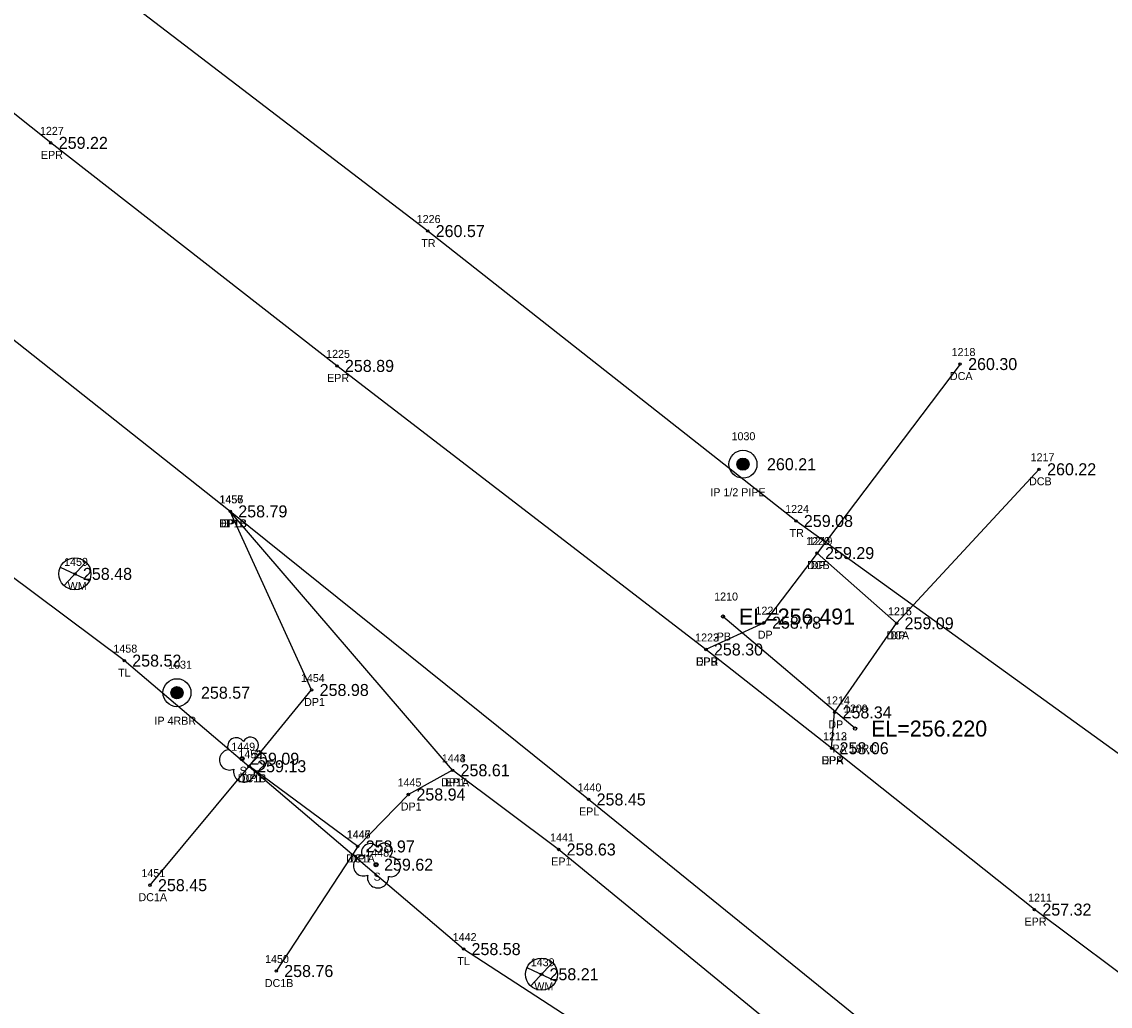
# Model space of a CAD drawing. Extents: x 1961231 to 1962574, y 799865 to 801120.
# Drawn here: x 1961812.2 to 1961948.3, y 800591.6 to 800714.6 of the extents above; entities that cross this region are included whole.
import ezdxf

# ---------------------------------------------------------------- set-up
doc = ezdxf.new("R2010")
doc.units = 0
for name, color, linetype in [('RD_EX_Conc', 7, 'Continuous'), ('RD_EX_Conc_txCode', 7, 'Continuous'), ('RD_EX_DR_Pipe', 7, 'Continuous'), ('RD_EX_DR_Pipe_txCode', 7, 'Continuous'), ('RD_EX_Driveway', 7, 'Continuous'), ('RD_EX_Driveway_txCode', 7, 'Continuous'), ('RD_EX_DV_Prop_txCode', 7, 'Continuous'), ('RD_EX_DV_PropPin', 7, 'Continuous'), ('RD_EX_Road', 7, 'Continuous'), ('RD_EX_Road_txCode', 7, 'Continuous'), ('RD_EX_TX_Conc_ELEV', 7, 'Continuous'), ('RD_EX_TX_Driveway_ELEV', 7, 'Continuous'), ('RD_EX_TX_DV_Prop_ELEV', 7, 'Continuous'), ('RD_EX_TX_Road_ELEV', 7, 'Continuous'), ('RD_EX_TX_UT_ELEV', 7, 'Continuous'), ('RD_EX_TX_VEG_ELEV', 7, 'Continuous'), ('RD_EX_UT', 7, 'Continuous'), ('RD_EX_UT_txCode', 7, 'Continuous'), ('RD_EX_VEG', 7, 'Continuous'), ('RD_EX_VEG_txCode', 7, 'Continuous'), ('RD_SMD_Locator', 7, 'Continuous'), ('RD_TX_Pipe_ElevEX', 7, 'Continuous')]:
    doc.layers.add(name, color=color, linetype=linetype)

msp = doc.modelspace()

# ---------------------------------------------------------------- linework, layer by layer
at = {"layer": 'RD_EX_Conc'}
for p, q in [((1961929.49, 800671.84), (1961911.62, 800648.22)), ((1961921.55, 800639.44), (1961939.36, 800658.69)), ((1961828.26, 800606.72), (1961840.65, 800621.58)), ((1961854.21, 800611.56), (1961844.03, 800595.99))]:
    msp.add_line(p, q, dxfattribs=at)
at = {"layer": 'RD_EX_DR_Pipe'}
msp.add_line((1961916.37, 800626.29), (1961899.86, 800640.29), dxfattribs=at)
at = {"layer": 'RD_EX_Driveway'}
for points in [[(1961866.07, 800621.08), (1961860.55, 800618.05), (1961854.21, 800611.56), (1961840.65, 800621.58), (1961848.46, 800631.11), (1961838.29, 800653.43)], [(1961913.43, 800623.83), (1961913.8, 800628.31), (1961921.55, 800639.44), (1961911.62, 800648.22), (1961904.99, 800639.52), (1961897.73, 800636.17)]]:
    msp.add_lwpolyline(points, dxfattribs=at)
at = {"layer": 'RD_EX_DV_PropPin'}
for p, q in [((1961902.15, 800658.59), (1961902.15, 800660.06)), ((1961902.18, 800658.58), (1961902.18, 800660.06)), ((1961902.22, 800658.58), (1961902.22, 800660.07)), ((1961902.25, 800658.57), (1961902.25, 800660.08)), ((1961902.29, 800658.57), (1961902.29, 800660.08)), ((1961902.32, 800658.56), (1961902.32, 800660.08)), ((1961902.36, 800658.56), (1961902.36, 800660.08)), ((1961902.39, 800658.56), (1961902.39, 800660.08)), ((1961902.43, 800658.57), (1961902.43, 800660.08)), ((1961902.46, 800658.57), (1961902.46, 800660.08)), ((1961902.5, 800658.58), (1961902.5, 800660.07)), ((1961902.53, 800658.58), (1961902.53, 800660.06)), ((1961902.57, 800658.59), (1961902.57, 800660.06)), ((1961901.62, 800659.13), (1961901.62, 800659.52)), ((1961901.66, 800659.03), (1961901.66, 800659.62)), ((1961901.69, 800658.95), (1961901.69, 800659.69)), ((1961901.73, 800658.9), (1961901.73, 800659.75)), ((1961901.76, 800658.85), (1961901.76, 800659.8)), ((1961901.8, 800658.81), (1961901.8, 800659.84)), ((1961901.83, 800658.77), (1961901.83, 800659.87)), ((1961901.87, 800658.74), (1961901.87, 800659.91)), ((1961901.9, 800658.71), (1961901.9, 800659.93)), ((1961901.94, 800658.69), (1961901.94, 800659.96)), ((1961901.97, 800658.67), (1961901.97, 800659.98)), ((1961902.01, 800658.65), (1961902.01, 800660)), ((1961902.04, 800658.63), (1961902.04, 800660.02)), ((1961902.08, 800658.62), (1961902.08, 800660.03)), ((1961902.11, 800658.6), (1961902.11, 800660.04)), ((1961902.6, 800658.6), (1961902.6, 800660.04)), ((1961902.64, 800658.62), (1961902.64, 800660.03)), ((1961902.67, 800658.63), (1961902.67, 800660.02)), ((1961902.71, 800658.65), (1961902.71, 800660)), ((1961902.74, 800658.67), (1961902.74, 800659.98)), ((1961902.78, 800658.69), (1961902.78, 800659.96)), ((1961902.81, 800658.71), (1961902.81, 800659.93)), ((1961902.85, 800658.74), (1961902.85, 800659.91)), ((1961902.88, 800658.77), (1961902.88, 800659.87)), ((1961902.92, 800658.81), (1961902.92, 800659.84)), ((1961902.95, 800658.85), (1961902.95, 800659.8)), ((1961902.99, 800658.9), (1961902.99, 800659.75)), ((1961903.02, 800658.95), (1961903.02, 800659.69)), ((1961903.06, 800659.03), (1961903.06, 800659.62)), ((1961903.09, 800659.13), (1961903.09, 800659.52)), ((1961831.42, 800630.03), (1961831.42, 800631.5)), ((1961831.46, 800630.02), (1961831.46, 800631.51)), ((1961831.49, 800630.02), (1961831.49, 800631.51)), ((1961831.53, 800630.01), (1961831.53, 800631.52)), ((1961831.56, 800630.01), (1961831.56, 800631.52)), ((1961831.6, 800630.01), (1961831.6, 800631.53)), ((1961831.63, 800630), (1961831.63, 800631.53)), ((1961831.67, 800630.01), (1961831.67, 800631.53)), ((1961831.7, 800630.01), (1961831.7, 800631.52)), ((1961831.74, 800630.01), (1961831.74, 800631.52)), ((1961831.77, 800630.02), (1961831.77, 800631.51)), ((1961831.81, 800630.02), (1961831.81, 800631.51)), ((1961831.84, 800630.03), (1961831.84, 800631.5)), ((1961830.9, 800630.57), (1961830.9, 800630.96)), ((1961830.93, 800630.47), (1961830.93, 800631.06)), ((1961830.97, 800630.4), (1961830.97, 800631.13)), ((1961831, 800630.34), (1961831, 800631.19)), ((1961831.04, 800630.29), (1961831.04, 800631.24)), ((1961831.07, 800630.25), (1961831.07, 800631.28)), ((1961831.11, 800630.21), (1961831.11, 800631.32)), ((1961831.14, 800630.18), (1961831.14, 800631.35)), ((1961831.18, 800630.16), (1961831.18, 800631.38)), ((1961831.21, 800630.13), (1961831.21, 800631.4)), ((1961831.25, 800630.11), (1961831.25, 800631.42)), ((1961831.28, 800630.09), (1961831.28, 800631.44)), ((1961831.32, 800630.07), (1961831.32, 800631.46)), ((1961831.35, 800630.06), (1961831.35, 800631.47)), ((1961831.39, 800630.04), (1961831.39, 800631.49)), ((1961831.88, 800630.04), (1961831.88, 800631.49)), ((1961831.91, 800630.06), (1961831.91, 800631.47)), ((1961831.95, 800630.07), (1961831.95, 800631.46)), ((1961831.98, 800630.09), (1961831.98, 800631.44)), ((1961832.02, 800630.11), (1961832.02, 800631.42)), ((1961832.05, 800630.13), (1961832.05, 800631.4)), ((1961832.09, 800630.16), (1961832.09, 800631.38)), ((1961832.12, 800630.18), (1961832.12, 800631.35)), ((1961832.16, 800630.21), (1961832.16, 800631.32)), ((1961832.19, 800630.25), (1961832.19, 800631.28)), ((1961832.23, 800630.29), (1961832.23, 800631.24)), ((1961832.26, 800630.34), (1961832.26, 800631.19)), ((1961832.3, 800630.4), (1961832.3, 800631.13)), ((1961832.33, 800630.47), (1961832.33, 800631.06)), ((1961832.37, 800630.57), (1961832.37, 800630.96))]:
    msp.add_line(p, q, dxfattribs=at)
for centre, radius in [((1961902.36, 800659.32), 1.75), ((1961902.36, 800659.32), 0.761), ((1961831.63, 800630.77), 1.75), ((1961831.63, 800630.77), 0.761)]:
    msp.add_circle(centre, radius, dxfattribs=at)
at = {"layer": 'RD_EX_Road'}
for points in [[(1962276.74, 800366.53), (1962275.76, 800367.28), (1962226.46, 800400.66), (1962183.05, 800429.73), (1962145.98, 800455.38), (1962104.4, 800484.06), (1962056.77, 800517.94), (1962023.95, 800541.05), (1961991.87, 800563.56), (1961983.89, 800569.94), (1961938.77, 800603.67), (1961913.43, 800623.83), (1961897.73, 800636.17), (1961851.62, 800671.61), (1961815.86, 800699.48), (1961795.77, 800715.49), (1961771.88, 800733.73), (1961750.77, 800750.96), (1961735.63, 800762.82), (1961702.92, 800788.52)], [(1962241.79, 800315.68), (1962238.35, 800317.6), (1962189.92, 800352.69), (1962151.64, 800383.49), (1962113.78, 800416.39), (1962074.11, 800451.29), (1962034.78, 800486.96), (1962017.07, 800503.17), (1961999.46, 800519.25), (1961962.48, 800552.12), (1961937.08, 800573.11), (1961923.19, 800584.9), (1961883.07, 800617.43), (1961838.29, 800653.43), (1961801.42, 800682.57), (1961728.41, 800740.86), (1961722.95, 800745.11), (1961689.13, 800771.93)], [(1961992.53, 800418.34), (1962000.94, 800437), (1962011.01, 800464.81), (1962016.84, 800481.64), (1962015.31, 800499.65), (1961996.99, 800516.71), (1961979.47, 800530.76), (1961969.8, 800538.75), (1961958.28, 800547.16), (1961941.07, 800560.82), (1961925.41, 800573.41), (1961918.19, 800579.25), (1961879.32, 800611.18), (1961866.07, 800621.08), (1961838.29, 800653.43)]]:
    msp.add_lwpolyline(points, dxfattribs=at)
at = {"layer": 'RD_EX_UT'}
for p, q in [((1961817.05, 800646.46), (1961820.68, 800644.75)), ((1961817.53, 800644.16), (1961820.19, 800647.06)), ((1961875.35, 800596.42), (1961878.98, 800594.71)), ((1961875.83, 800594.13), (1961878.5, 800597.02))]:
    msp.add_line(p, q, dxfattribs=at)
for centre in [(1961818.88, 800645.62), (1961877.18, 800595.59)]:
    msp.add_circle(centre, 2, dxfattribs=at)
at = {"layer": 'RD_EX_VEG'}
for points in [[(1961991.65, 800601.73), (1961952.54, 800620.78), (1961908.97, 800652.23), (1961862.96, 800688.46), (1961806.36, 800731.71)], [(1961986.16, 800417.05), (1962008.73, 800486.69), (1961986.14, 800509.28), (1961949.4, 800540.42), (1961909.42, 800571.42), (1961867.44, 800598.73), (1961825.04, 800634.78), (1961788.24, 800662.23), (1961745.49, 800697.38)]]:
    msp.add_lwpolyline(points, dxfattribs=at)
for centre in [(1961839.77, 800622.52), (1961856.51, 800609.28)]:
    msp.add_circle(centre, 0.25, dxfattribs=at)
for centre, radius, start, end in [((1961839.04, 800624.07), 1.08, 34.9763, 204.756), ((1961840.81, 800624.22), 0.995, 308.7626, 152.0467), ((1961838.2, 800622.37), 1.26, 96.4518, 294.734), ((1961841.6, 800622.24), 1.22, 256.5667, 98.1046), ((1961840.01, 800620.92), 1.32, 166.8827, 5.7589), ((1961855.78, 800610.83), 1.08, 34.9763, 204.756), ((1961857.55, 800610.98), 0.995, 308.7626, 152.0467), ((1961854.94, 800609.13), 1.26, 96.4518, 294.734), ((1961858.34, 800609), 1.22, 256.5667, 98.1046), ((1961856.75, 800607.69), 1.32, 166.8827, 5.7589)]:
    msp.add_arc(centre, radius, start, end, dxfattribs=at)
at = {"layer": 'RD_SMD_Locator'}
for centre, radius in [((1961815.86, 800699.48), 0.15), ((1961862.96, 800688.46), 0.15), ((1961851.62, 800671.61), 0.15), ((1961929.49, 800671.84), 0.15), ((1961902.36, 800659.32), 0.15), ((1961939.36, 800658.69), 0.15), ((1961838.29, 800653.43), 0.15), ((1961838.29, 800653.43), 0.15), ((1961838.29, 800653.43), 0.15), ((1961908.97, 800652.23), 0.15), ((1961911.62, 800648.22), 0.15), ((1961911.62, 800648.22), 0.15), ((1961818.88, 800645.62), 0.15), ((1961899.86, 800640.29), 0.2), ((1961904.99, 800639.52), 0.15), ((1961921.55, 800639.44), 0.15), ((1961921.55, 800639.44), 0.15), ((1961897.73, 800636.17), 0.15), ((1961897.73, 800636.17), 0.15), ((1961825.04, 800634.78), 0.15), ((1961831.63, 800630.77), 0.15), ((1961848.46, 800631.11), 0.15), ((1961913.8, 800628.31), 0.15), ((1961916.37, 800626.29), 0.2), ((1961913.43, 800623.83), 0.15), ((1961913.43, 800623.83), 0.15), ((1961839.77, 800622.52), 0.15), ((1961840.65, 800621.58), 0.15), ((1961840.65, 800621.58), 0.15), ((1961866.07, 800621.08), 0.15), ((1961866.07, 800621.08), 0.15), ((1961860.55, 800618.05), 0.15), ((1961883.07, 800617.43), 0.15), ((1961854.21, 800611.56), 0.15), ((1961854.21, 800611.56), 0.15), ((1961879.32, 800611.18), 0.15), ((1961856.51, 800609.28), 0.15), ((1961828.26, 800606.72), 0.15), ((1961938.77, 800603.67), 0.15), ((1961867.44, 800598.73), 0.15), ((1961844.03, 800595.99), 0.15), ((1961877.18, 800595.59), 0.15)]:
    msp.add_circle(centre, radius, dxfattribs=at)

# ---------------------------------------------------------------- texts
at = {"layer": 'RD_EX_Conc_txCode'}
for s, p in [('1218', (1961928.43, 800672.84)), ('DCA', (1961928.22, 800669.84)), ('1217', (1961938.3, 800659.69)), ('DCB', (1961938.11, 800656.69)), ('1219', (1961910.56, 800649.22)), ('DCB', (1961910.37, 800646.22)), ('1216', (1961920.47, 800640.44)), ('DCA', (1961920.29, 800637.44)), ('1452', (1961839.31, 800622.58)), ('DC1B', (1961839.24, 800619.58)), ('1447', (1961852.86, 800612.56)), ('DC1A', (1961852.78, 800609.56)), ('1451', (1961827.19, 800607.72)), ('DC1A', (1961826.82, 800604.72)), ('1450', (1961842.64, 800596.99)), ('DC1B', (1961842.61, 800593.99))]:
    msp.add_text(s, height=1, dxfattribs=at).set_placement(p)
at = {"layer": 'RD_EX_DR_Pipe_txCode'}
for s, p in [('1210', (1961898.76, 800642.29)), ('PB', (1961899.08, 800637.29)), ('1209', (1961914.98, 800628.29)), ('PA 18RC', (1961913.53, 800623.29))]:
    msp.add_text(s, height=1, dxfattribs=at).set_placement(p)
at = {"layer": 'RD_EX_Driveway_txCode'}
for s, p in [('1455', (1961836.95, 800654.43)), ('DP1B', (1961836.88, 800651.43)), ('1220', (1961910.24, 800649.22)), ('DP', (1961910.84, 800646.22)), ('1221', (1961903.92, 800640.52)), ('1215', (1961920.49, 800640.44)), ('DP', (1961904.21, 800637.52)), ('DP', (1961920.77, 800637.44)), ('1222', (1961896.38, 800637.17)), ('DPB', (1961896.47, 800634.17)), ('1454', (1961847.12, 800632.11)), ('1214', (1961912.74, 800629.31)), ('DP1', (1961847.52, 800629.11)), ('DP', (1961913.02, 800626.31)), ('1213', (1961912.37, 800624.83)), ('1453', (1961839.31, 800622.58)), ('1444', (1961864.73, 800622.08)), ('DPA', (1961912.17, 800621.83)), ('DP1', (1961839.71, 800619.58)), ('1445', (1961859.2, 800619.05)), ('DP1A', (1961864.64, 800619.08)), ('DP1', (1961859.6, 800616.05)), ('1446', (1961852.84, 800612.56)), ('DP1', (1961853.27, 800609.56))]:
    msp.add_text(s, height=1, dxfattribs=at).set_placement(p)
at = {"layer": 'RD_EX_DV_Prop_txCode'}
for s, p in [('1030', (1961900.93, 800662.32)), ('IP 1/2 PIPE', (1961898.28, 800655.32)), ('1031', (1961830.53, 800633.77)), ('IP 4RBR', (1961828.82, 800626.77))]:
    msp.add_text(s, height=1, dxfattribs=at).set_placement(p)
at = {"layer": 'RD_EX_Road_txCode'}
for s, p in [('1227', (1961814.51, 800700.48)), ('EPR', (1961814.63, 800697.48)), ('1225', (1961850.27, 800672.61)), ('EPR', (1961850.39, 800669.61)), ('1456', (1961836.92, 800654.43)), ('1457', (1961836.95, 800654.43)), ('EP1B', (1961836.9, 800651.43)), ('EPL', (1961837.09, 800651.43)), ('1223', (1961896.38, 800637.17)), ('EPR', (1961896.5, 800634.17)), ('1212', (1961912.37, 800624.83)), ('1443', (1961864.73, 800622.08)), ('EPR', (1961912.2, 800621.83)), ('EP1', (1961865.15, 800619.08)), ('1440', (1961881.69, 800618.43)), ('EPL', (1961881.87, 800615.43)), ('1441', (1961878.26, 800612.18)), ('EP1', (1961878.4, 800609.18)), ('1211', (1961937.99, 800604.67)), ('EPR', (1961937.54, 800601.67))]:
    msp.add_text(s, height=1, dxfattribs=at).set_placement(p)
at = {"layer": 'RD_EX_TX_Conc_ELEV'}
for s, p in [('260.30', (1961930.49, 800671.09)), ('260.22', (1961940.36, 800657.94)), ('259.29', (1961912.62, 800647.47)), ('259.09', (1961922.55, 800638.69)), ('259.13', (1961841.65, 800620.83)), ('258.97', (1961855.21, 800610.81)), ('258.45', (1961829.26, 800605.97)), ('258.76', (1961845.03, 800595.24))]:
    msp.add_text(s, height=1.5, dxfattribs=at).set_placement(p)
at = {"layer": 'RD_EX_TX_Driveway_ELEV'}
for s, p in [('258.79', (1961839.29, 800652.68)), ('259.29', (1961912.62, 800647.47)), ('258.78', (1961905.99, 800638.77)), ('259.09', (1961922.55, 800638.69)), ('258.30', (1961898.73, 800635.42)), ('258.98', (1961849.46, 800630.36)), ('258.34', (1961914.8, 800627.56)), ('258.06', (1961914.43, 800623.08)), ('259.13', (1961841.65, 800620.83)), ('258.61', (1961867.07, 800620.33)), ('258.94', (1961861.55, 800617.3)), ('258.97', (1961855.21, 800610.81))]:
    msp.add_text(s, height=1.5, dxfattribs=at).set_placement(p)
at = {"layer": 'RD_EX_TX_DV_Prop_ELEV'}
for s, p in [('260.21', (1961905.36, 800658.57)), ('258.57', (1961834.63, 800630.02))]:
    msp.add_text(s, height=1.5, dxfattribs=at).set_placement(p)
at = {"layer": 'RD_EX_TX_Road_ELEV'}
for s, p in [('259.22', (1961816.86, 800698.73)), ('258.89', (1961852.62, 800670.86)), ('258.79', (1961839.29, 800652.68)), ('258.79', (1961839.29, 800652.68)), ('258.30', (1961898.73, 800635.42)), ('258.06', (1961914.43, 800623.08)), ('258.61', (1961867.07, 800620.33)), ('258.45', (1961884.07, 800616.68)), ('258.63', (1961880.32, 800610.43)), ('257.32', (1961939.77, 800602.92))]:
    msp.add_text(s, height=1.5, dxfattribs=at).set_placement(p)
at = {"layer": 'RD_EX_TX_UT_ELEV'}
for s, p in [('258.48', (1961819.88, 800644.87)), ('258.21', (1961878.18, 800594.84))]:
    msp.add_text(s, height=1.5, dxfattribs=at).set_placement(p)
at = {"layer": 'RD_EX_TX_VEG_ELEV'}
for s, p in [('260.57', (1961863.96, 800687.71)), ('259.08', (1961909.97, 800651.48)), ('258.52', (1961826.04, 800634.03)), ('259.09', (1961840.77, 800621.77)), ('259.62', (1961857.51, 800608.53)), ('258.58', (1961868.44, 800597.98))]:
    msp.add_text(s, height=1.5, dxfattribs=at).set_placement(p)
at = {"layer": 'RD_EX_UT_txCode'}
for s, p in [('1459', (1961817.53, 800646.62)), ('WM', (1961817.97, 800643.62)), ('1439', (1961875.84, 800596.59)), ('WM', (1961876.28, 800593.59))]:
    msp.add_text(s, height=1, dxfattribs=at).set_placement(p)
at = {"layer": 'RD_EX_VEG_txCode'}
for s, p in [('1226', (1961861.59, 800689.46)), ('TR', (1961862.16, 800686.46)), ('1224', (1961907.63, 800653.23)), ('TR', (1961908.18, 800650.23)), ('1458', (1961823.69, 800635.78)), ('TL', (1961824.27, 800632.78)), ('1449', (1961838.42, 800623.52)), ('S', (1961839.46, 800620.52)), ('1448', (1961855.16, 800610.28)), ('S', (1961856.2, 800607.28)), ('1442', (1961866.09, 800599.73)), ('TL', (1961866.67, 800596.73))]:
    msp.add_text(s, height=1, dxfattribs=at).set_placement(p)
at = {"layer": 'RD_TX_Pipe_ElevEX'}
for s, p in [('EL=256.491', (1961901.86, 800639.29)), ('EL=256.220', (1961918.37, 800625.29))]:
    msp.add_text(s, height=2, dxfattribs=at).set_placement(p)

doc.saveas('drawing.dxf')
